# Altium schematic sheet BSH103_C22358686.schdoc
size 127 x 101 mm
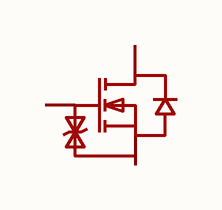
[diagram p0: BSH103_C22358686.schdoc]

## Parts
Q?  bsh103  [SOT-23-3_L2.9-W1.3-P1.90-LS2.4-BR]  (value not drawn)

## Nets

Not connected (* = marked no-connect by the designer): Q? 1(G) 2(S) 3(D)

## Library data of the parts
Q? = bsh103: 漏源电压(Vdss):30V;连续漏极电流(Id):850mA;导通电阻(RDS(on)):650mΩ@2.5V;耗散功率(Pd):360mW;阈值电压(Vgs(th)):1.2V@250uA;; Manufacturer: TECH PUBLIC(台舟); Symbol: BSH103_C22358686; AddInBom: yes; ModelId: c62791f0466c4ae2a892c056b845b0ca; ModelName: SOT-23-3P_L2.9-W1.3-H1.0-LS2.4-P0.95; ModelTransform: 98.425,114.173,0,180,0,0,0.0005,-0.0005,0; Drain to Source Voltage: 30V; Current - Continuous Drain(Id): 850mA; Pd - Power Dissipation: 360mW; Gate Charge(Qg): 5.2nC@4.5V; Input Capacitance(Ciss): 146pF; Reverse Transfer Capacitance (Crss@Vds): 14.8pF; Output Capacitance(Coss): 36.6pF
